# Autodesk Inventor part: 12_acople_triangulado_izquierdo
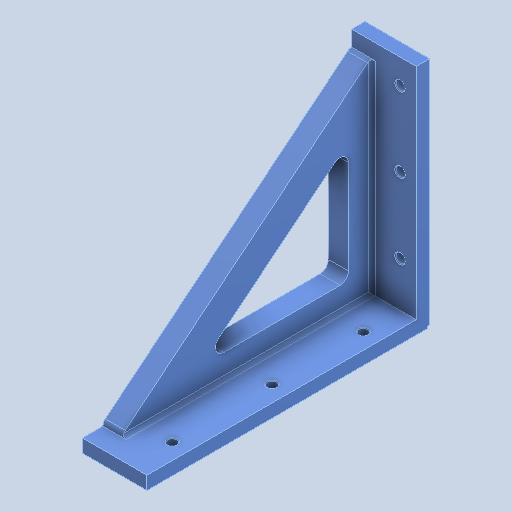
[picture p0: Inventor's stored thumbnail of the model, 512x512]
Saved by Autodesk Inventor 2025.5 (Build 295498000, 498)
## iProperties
Created: 2026-10
Part Number: 12_acople_triangulado_izquierdo
Material: Genérico
Document SubType Name: Modeling
Designer: Luis M
Density: 1 g/cm^3
Appearance: Valor por defecto
Author: Luis M
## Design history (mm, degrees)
feature "Base1"
node "Sólido1"
